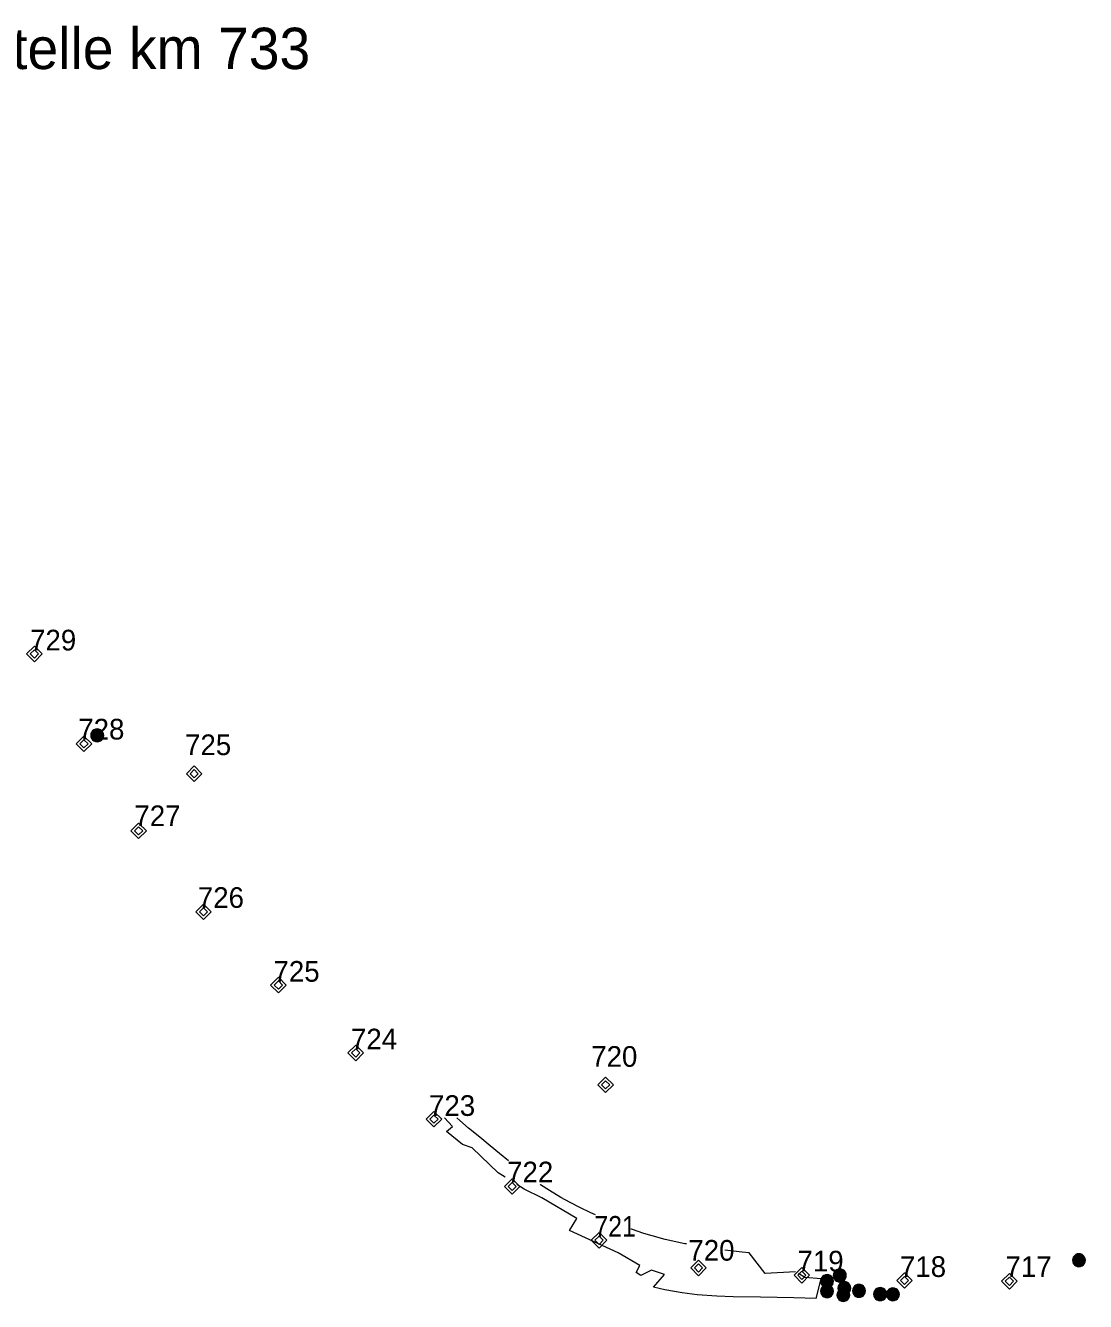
# Model space of a CAD drawing. Extents: x 3461750 to 3585707, y 5917729 to 5985917.
# Drawn here: x 3480178 to 3490431, y 5967330 to 5979672 of the extents above; entities that cross this region are included whole.
import ezdxf

# ---------------------------------------------------------------- set-up
doc = ezdxf.new("R2010")
doc.units = 0
doc.header["$LTSCALE"] = 80
doc.layers.add('11', color=7, linetype='Continuous')
for name, color, linetype, lineweight in [('12', 7, 'Continuous', 13), ('13', 7, 'Continuous', 13), ('14', 7, 'Continuous', 13), ('15', 7, 'Continuous', 13), ('2', 7, 'Continuous', 13), ('3', 7, 'Continuous', 13)]:
    doc.layers.add(name, color=color, linetype=linetype, lineweight=lineweight)

msp = doc.modelspace()

# ---------------------------------------------------------------- hatches: boundary and pattern name
at = {"layer": '3'}
for points in [[(3480934.61, 5972805.43), (3480931.68, 5972822.05), (3480925.43, 5972837.15), (3480915.49, 5972850.11), (3480902.53, 5972860.05), (3480887.44, 5972866.3), (3480871.24, 5972868.43), (3480855.04, 5972866.3), (3480839.95, 5972860.05), (3480826.99, 5972850.11), (3480817.05, 5972837.15), (3480810.8, 5972822.05), (3480808.66, 5972805.86), (3480810.8, 5972789.66), (3480817.05, 5972774.57), (3480826.99, 5972761.61), (3480839.95, 5972751.67), (3480855.04, 5972745.42), (3480871.24, 5972743.28), (3480887.44, 5972745.42), (3480902.53, 5972751.67), (3480915.49, 5972761.61), (3480925.43, 5972774.57), (3480931.68, 5972789.66)], [(3490431.29, 5967728.57), (3490428.36, 5967745.2), (3490422.11, 5967760.29), (3490412.17, 5967773.25), (3490399.21, 5967783.2), (3490384.12, 5967789.45), (3490367.92, 5967791.58), (3490351.72, 5967789.45), (3490336.63, 5967783.2), (3490323.67, 5967773.25), (3490313.73, 5967760.29), (3490307.48, 5967745.2), (3490305.34, 5967729), (3490307.48, 5967712.81), (3490313.73, 5967697.72), (3490323.67, 5967684.76), (3490336.63, 5967674.81), (3490351.72, 5967668.56), (3490367.92, 5967666.43), (3490384.12, 5967668.56), (3490399.21, 5967674.81), (3490412.17, 5967684.76), (3490422.11, 5967697.72), (3490428.36, 5967712.81)], [(3487994.96, 5967526.52), (3487992.03, 5967543.15), (3487985.78, 5967558.24), (3487975.84, 5967571.2), (3487962.88, 5967581.14), (3487947.79, 5967587.4), (3487931.59, 5967589.53), (3487915.4, 5967587.4), (3487900.3, 5967581.14), (3487887.34, 5967571.2), (3487877.4, 5967558.24), (3487871.15, 5967543.15), (3487869.02, 5967526.95), (3487871.15, 5967510.76), (3487877.4, 5967495.67), (3487887.34, 5967482.71), (3487900.3, 5967472.76), (3487915.4, 5967466.51), (3487931.59, 5967464.38), (3487947.79, 5967466.51), (3487962.88, 5967472.76), (3487975.84, 5967482.71), (3487985.78, 5967495.67), (3487992.03, 5967510.76)], [(3488117.72, 5967581.7), (3488114.79, 5967598.32), (3488108.54, 5967613.42), (3488098.59, 5967626.38), (3488085.63, 5967636.32), (3488070.54, 5967642.57), (3488054.35, 5967644.7), (3488038.15, 5967642.57), (3488023.06, 5967636.32), (3488010.1, 5967626.38), (3488000.15, 5967613.42), (3487993.9, 5967598.32), (3487991.77, 5967582.13), (3487993.9, 5967565.93), (3488000.15, 5967550.84), (3488010.1, 5967537.88), (3488023.06, 5967527.94), (3488038.15, 5967521.69), (3488054.35, 5967519.55), (3488070.54, 5967521.69), (3488085.63, 5967527.94), (3488098.59, 5967537.88), (3488108.54, 5967550.84), (3488114.79, 5967565.93)], [(3487994.82, 5967429.26), (3487991.89, 5967445.88), (3487985.64, 5967460.98), (3487975.69, 5967473.94), (3487962.73, 5967483.88), (3487947.64, 5967490.13), (3487931.44, 5967492.26), (3487915.25, 5967490.13), (3487900.16, 5967483.88), (3487887.2, 5967473.94), (3487877.25, 5967460.98), (3487871, 5967445.88), (3487868.87, 5967429.69), (3487871, 5967413.49), (3487877.25, 5967398.4), (3487887.2, 5967385.44), (3487900.16, 5967375.5), (3487915.25, 5967369.25), (3487931.44, 5967367.11), (3487947.64, 5967369.25), (3487962.73, 5967375.5), (3487975.69, 5967385.44), (3487985.64, 5967398.4), (3487991.89, 5967413.49)], [(3488152, 5967392.25), (3488149.07, 5967408.87), (3488142.81, 5967423.96), (3488132.87, 5967436.92), (3488119.91, 5967446.87), (3488104.82, 5967453.12), (3488088.62, 5967455.25), (3488072.43, 5967453.12), (3488057.34, 5967446.87), (3488044.38, 5967436.92), (3488034.43, 5967423.96), (3488028.18, 5967408.87), (3488026.05, 5967392.68), (3488028.18, 5967376.48), (3488034.43, 5967361.39), (3488044.38, 5967348.43), (3488057.34, 5967338.48), (3488072.43, 5967332.23), (3488088.62, 5967330.1), (3488104.82, 5967332.23), (3488119.91, 5967338.48), (3488132.87, 5967348.43), (3488142.81, 5967361.39), (3488149.07, 5967376.48)], [(3488162.05, 5967458.36), (3488159.12, 5967474.98), (3488152.87, 5967490.08), (3488142.93, 5967503.04), (3488129.97, 5967512.98), (3488114.88, 5967519.23), (3488098.68, 5967521.36), (3488082.49, 5967519.23), (3488067.39, 5967512.98), (3488054.43, 5967503.04), (3488044.49, 5967490.08), (3488038.24, 5967474.98), (3488036.11, 5967458.79), (3488038.24, 5967442.59), (3488044.49, 5967427.5), (3488054.43, 5967414.54), (3488067.39, 5967404.6), (3488082.49, 5967398.35), (3488098.68, 5967396.21), (3488114.88, 5967398.35), (3488129.97, 5967404.6), (3488142.93, 5967414.54), (3488152.87, 5967427.5), (3488159.12, 5967442.59)], [(3488303.46, 5967432.68), (3488300.53, 5967449.3), (3488294.28, 5967464.39), (3488284.34, 5967477.35), (3488271.38, 5967487.3), (3488256.28, 5967493.55), (3488240.09, 5967495.68), (3488223.89, 5967493.55), (3488208.8, 5967487.3), (3488195.84, 5967477.35), (3488185.9, 5967464.39), (3488179.65, 5967449.3), (3488177.51, 5967433.1), (3488179.65, 5967416.91), (3488185.9, 5967401.82), (3488195.84, 5967388.86), (3488208.8, 5967378.91), (3488223.89, 5967372.66), (3488240.09, 5967370.53), (3488256.28, 5967372.66), (3488271.38, 5967378.91), (3488284.34, 5967388.86), (3488294.28, 5967401.82), (3488300.53, 5967416.91)], [(3488508.2, 5967400.84), (3488505.27, 5967417.47), (3488499.02, 5967432.56), (3488489.07, 5967445.52), (3488476.11, 5967455.46), (3488461.02, 5967461.71), (3488444.82, 5967463.85), (3488428.63, 5967461.71), (3488413.54, 5967455.46), (3488400.58, 5967445.52), (3488390.63, 5967432.56), (3488384.38, 5967417.47), (3488382.25, 5967401.27), (3488384.38, 5967385.07), (3488390.63, 5967369.98), (3488400.58, 5967357.02), (3488413.54, 5967347.08), (3488428.63, 5967340.83), (3488444.82, 5967338.69), (3488461.02, 5967340.83), (3488476.11, 5967347.08), (3488489.07, 5967357.02), (3488499.02, 5967369.98), (3488505.27, 5967385.07)], [(3488631.83, 5967398.98), (3488628.9, 5967415.61), (3488622.65, 5967430.7), (3488612.7, 5967443.66), (3488599.74, 5967453.61), (3488584.65, 5967459.86), (3488568.46, 5967461.99), (3488552.26, 5967459.86), (3488537.17, 5967453.61), (3488524.21, 5967443.66), (3488514.27, 5967430.7), (3488508.01, 5967415.61), (3488505.88, 5967399.41), (3488508.01, 5967383.22), (3488514.27, 5967368.13), (3488524.21, 5967355.17), (3488537.17, 5967345.22), (3488552.26, 5967338.97), (3488568.46, 5967336.84), (3488584.65, 5967338.97), (3488599.74, 5967345.22), (3488612.7, 5967355.17), (3488622.65, 5967368.13), (3488628.9, 5967383.22)]]:
    msp.add_hatch(color=256, dxfattribs=at).paths.add_polyline_path(points)

# ---------------------------------------------------------------- linework, layer by layer
at = {"layer": '12'}
for points in [[(3481808.63, 5972509.77), (3481733.54, 5972434.68), (3481808.63, 5972359.59), (3481883.72, 5972434.68)], [(3481808.63, 5972474.37), (3481768.93, 5972434.68), (3481808.63, 5972394.99), (3481848.32, 5972434.68)]]:
    msp.add_lwpolyline(points, close=True, dxfattribs=at)
at = {"layer": '13'}
for points in [[(3485789.1, 5969500.4), (3485714, 5969425.31), (3485789.1, 5969350.22), (3485864.19, 5969425.31)], [(3485789.1, 5969465), (3485749.4, 5969425.31), (3485789.1, 5969385.61), (3485828.79, 5969425.31)]]:
    msp.add_lwpolyline(points, close=True, dxfattribs=at)
at = {"layer": '14'}
for points in [[(3486687.92, 5967729.89), (3486612.83, 5967654.8), (3486687.92, 5967579.71), (3486763.01, 5967654.8)], [(3486687.92, 5967694.49), (3486648.23, 5967654.8), (3486687.92, 5967615.1), (3486727.62, 5967654.8)]]:
    msp.add_lwpolyline(points, close=True, dxfattribs=at)
at = {"layer": '15'}
for points in [[(3480263.9, 5973668.36), (3480188.81, 5973593.27), (3480263.9, 5973518.18), (3480338.99, 5973593.27)], [(3480263.9, 5973632.97), (3480224.21, 5973593.27), (3480263.9, 5973553.58), (3480303.59, 5973593.27)], [(3480742.71, 5972799.13), (3480667.62, 5972724.04), (3480742.71, 5972648.95), (3480817.8, 5972724.04)], [(3480742.71, 5972763.73), (3480703.02, 5972724.04), (3480742.71, 5972684.34), (3480782.4, 5972724.04)], [(3481271.86, 5971958.21), (3481196.77, 5971883.12), (3481271.86, 5971808.03), (3481346.95, 5971883.12)], [(3481271.86, 5971922.81), (3481232.17, 5971883.12), (3481271.86, 5971843.43), (3481311.55, 5971883.12)], [(3481899.1, 5971173.83), (3481824.02, 5971098.74), (3481899.1, 5971023.65), (3481974.2, 5971098.74)], [(3481899.1, 5971138.44), (3481859.41, 5971098.74), (3481899.11, 5971059.05), (3481938.8, 5971098.74)], [(3482623.91, 5970466.41), (3482548.82, 5970391.32), (3482623.91, 5970316.23), (3482699, 5970391.32)], [(3482623.91, 5970431.01), (3482584.22, 5970391.32), (3482623.91, 5970351.63), (3482663.6, 5970391.32)], [(3483371.71, 5969809.28), (3483296.62, 5969734.19), (3483371.71, 5969659.1), (3483446.8, 5969734.19)], [(3483371.71, 5969773.88), (3483332.02, 5969734.19), (3483371.71, 5969694.5), (3483411.4, 5969734.19)], [(3484128.45, 5969168.17), (3484053.36, 5969093.08), (3484128.45, 5969017.99), (3484203.54, 5969093.08)], [(3484128.45, 5969132.77), (3484088.76, 5969093.08), (3484128.45, 5969053.39), (3484168.14, 5969093.08)], [(3484885.34, 5968517.97), (3484810.24, 5968442.88), (3484885.34, 5968367.79), (3484960.43, 5968442.88)], [(3484885.34, 5968482.58), (3484845.64, 5968442.88), (3484885.34, 5968403.19), (3484925.03, 5968442.88)], [(3485725.86, 5967996.78), (3485650.77, 5967921.69), (3485725.86, 5967846.6), (3485800.95, 5967921.69)], [(3485725.86, 5967961.38), (3485686.17, 5967921.69), (3485725.86, 5967882), (3485765.56, 5967921.69)], [(3487687.97, 5967658.89), (3487612.88, 5967583.8), (3487687.97, 5967508.71), (3487763.06, 5967583.8)], [(3487687.97, 5967623.49), (3487648.28, 5967583.8), (3487687.97, 5967544.11), (3487727.66, 5967583.8)], [(3488681.14, 5967608.11), (3488606.05, 5967533.02), (3488681.14, 5967457.93), (3488756.23, 5967533.02)], [(3489695.54, 5967600.88), (3489620.45, 5967525.79), (3489695.54, 5967450.7), (3489770.63, 5967525.79)], [(3488681.14, 5967572.71), (3488641.44, 5967533.02), (3488681.14, 5967493.33), (3488720.83, 5967533.02)], [(3489695.54, 5967565.49), (3489655.85, 5967525.79), (3489695.54, 5967486.1), (3489735.23, 5967525.79)]]:
    msp.add_lwpolyline(points, close=True, dxfattribs=at)
at = {"layer": '2'}
for points in [[(3484816.5, 5968533.05), (3484748.44, 5968575.98), (3484499.8, 5968815.14), (3484403.66, 5968847.75), (3484249.51, 5968974.71), (3484308.4, 5969022.27), (3484231.51, 5969105.2)], [(3484849.45, 5968692), (3484762.6, 5968761.13), (3484672.27, 5968834.28), (3484571.34, 5968917.97), (3484462.89, 5969007.23), (3484377.64, 5969080.57), (3484349.37, 5969105.2)], [(3486252.39, 5967467.09), (3486360.5, 5967591.5), (3486234.03, 5967632.52), (3486130.32, 5967582.03), (3486084.47, 5967610.35), (3486121.68, 5967676.86), (3485909.91, 5967802.25), (3485439.16, 5968016.7), (3485510.79, 5968132.81), (3485173.1, 5968331.84), (3485002.98, 5968415.43), (3484929.14, 5968462)], [(3485692.77, 5968166.8), (3485645.17, 5968188.77), (3485539.5, 5968238.67), (3485445.02, 5968288.87), (3485355.91, 5968337.11), (3485248.1, 5968402.25), (3485159.47, 5968459.67), (3485156.12, 5968462)], [(3486570.2, 5967886.35), (3486556.98, 5967888.77), (3486364.89, 5967928.91), (3486239.06, 5967963.67), (3486158.64, 5967988.57), (3486040.43, 5968028.52), (3486033.9, 5968030.88)], [(3487179.15, 5967799.22), (3487109.96, 5967805.57), (3486943.8, 5967825.8)], [(3487625.3, 5967616.61), (3487333.59, 5967599.22), (3487179.15, 5967799.22)], [(3487825.54, 5967357.91), (3487874.07, 5967549.51), (3487717.33, 5967562.99), (3487655.35, 5967600.5)], [(3487825.54, 5967357.91), (3487609.86, 5967363.87), (3487286.28, 5967372.27), (3487023.34, 5967374.71), (3486866.75, 5967380.37), (3486674.51, 5967395.02), (3486528.91, 5967413.48), (3486361.72, 5967443.36), (3486252.39, 5967467.09)]]:
    msp.add_lwpolyline(points, dxfattribs=at)
at = {"layer": '3'}
for points in [[(3480934.61, 5972805.43), (3480931.68, 5972822.05), (3480925.43, 5972837.15), (3480915.49, 5972850.11), (3480902.53, 5972860.05), (3480887.44, 5972866.3), (3480871.24, 5972868.43), (3480855.04, 5972866.3), (3480839.95, 5972860.05), (3480826.99, 5972850.11), (3480817.05, 5972837.15), (3480810.8, 5972822.05), (3480808.66, 5972805.86), (3480810.8, 5972789.66), (3480817.05, 5972774.57), (3480826.99, 5972761.61), (3480839.95, 5972751.67), (3480855.04, 5972745.42), (3480871.24, 5972743.28), (3480887.44, 5972745.42), (3480902.53, 5972751.67), (3480915.49, 5972761.61), (3480925.43, 5972774.57), (3480931.68, 5972789.66)], [(3490431.29, 5967728.57), (3490428.36, 5967745.2), (3490422.11, 5967760.29), (3490412.17, 5967773.25), (3490399.21, 5967783.2), (3490384.12, 5967789.45), (3490367.92, 5967791.58), (3490351.72, 5967789.45), (3490336.63, 5967783.2), (3490323.67, 5967773.25), (3490313.73, 5967760.29), (3490307.48, 5967745.2), (3490305.34, 5967729), (3490307.48, 5967712.81), (3490313.73, 5967697.72), (3490323.67, 5967684.76), (3490336.63, 5967674.81), (3490351.72, 5967668.56), (3490367.92, 5967666.43), (3490384.12, 5967668.56), (3490399.21, 5967674.81), (3490412.17, 5967684.76), (3490422.11, 5967697.72), (3490428.36, 5967712.81)], [(3487994.96, 5967526.52), (3487992.03, 5967543.15), (3487985.78, 5967558.24), (3487975.84, 5967571.2), (3487962.88, 5967581.14), (3487947.79, 5967587.4), (3487931.59, 5967589.53), (3487915.4, 5967587.4), (3487900.3, 5967581.14), (3487887.34, 5967571.2), (3487877.4, 5967558.24), (3487871.15, 5967543.15), (3487869.02, 5967526.95), (3487871.15, 5967510.76), (3487877.4, 5967495.67), (3487887.34, 5967482.71), (3487900.3, 5967472.76), (3487915.4, 5967466.51), (3487931.59, 5967464.38), (3487947.79, 5967466.51), (3487962.88, 5967472.76), (3487975.84, 5967482.71), (3487985.78, 5967495.67), (3487992.03, 5967510.76)], [(3488117.72, 5967581.7), (3488114.79, 5967598.32), (3488108.54, 5967613.42), (3488098.59, 5967626.38), (3488085.63, 5967636.32), (3488070.54, 5967642.57), (3488054.35, 5967644.7), (3488038.15, 5967642.57), (3488023.06, 5967636.32), (3488010.1, 5967626.38), (3488000.15, 5967613.42), (3487993.9, 5967598.32), (3487991.77, 5967582.13), (3487993.9, 5967565.93), (3488000.15, 5967550.84), (3488010.1, 5967537.88), (3488023.06, 5967527.94), (3488038.15, 5967521.69), (3488054.35, 5967519.55), (3488070.54, 5967521.69), (3488085.63, 5967527.94), (3488098.59, 5967537.88), (3488108.54, 5967550.84), (3488114.79, 5967565.93)], [(3487994.82, 5967429.26), (3487991.89, 5967445.88), (3487985.64, 5967460.98), (3487975.69, 5967473.94), (3487962.73, 5967483.88), (3487947.64, 5967490.13), (3487931.44, 5967492.26), (3487915.25, 5967490.13), (3487900.16, 5967483.88), (3487887.2, 5967473.94), (3487877.25, 5967460.98), (3487871, 5967445.88), (3487868.87, 5967429.69), (3487871, 5967413.49), (3487877.25, 5967398.4), (3487887.2, 5967385.44), (3487900.16, 5967375.5), (3487915.25, 5967369.25), (3487931.44, 5967367.11), (3487947.64, 5967369.25), (3487962.73, 5967375.5), (3487975.69, 5967385.44), (3487985.64, 5967398.4), (3487991.89, 5967413.49)], [(3488152, 5967392.25), (3488149.07, 5967408.87), (3488142.81, 5967423.96), (3488132.87, 5967436.92), (3488119.91, 5967446.87), (3488104.82, 5967453.12), (3488088.62, 5967455.25), (3488072.43, 5967453.12), (3488057.34, 5967446.87), (3488044.38, 5967436.92), (3488034.43, 5967423.96), (3488028.18, 5967408.87), (3488026.05, 5967392.68), (3488028.18, 5967376.48), (3488034.43, 5967361.39), (3488044.38, 5967348.43), (3488057.34, 5967338.48), (3488072.43, 5967332.23), (3488088.62, 5967330.1), (3488104.82, 5967332.23), (3488119.91, 5967338.48), (3488132.87, 5967348.43), (3488142.81, 5967361.39), (3488149.07, 5967376.48)], [(3488162.05, 5967458.36), (3488159.12, 5967474.98), (3488152.87, 5967490.08), (3488142.93, 5967503.04), (3488129.97, 5967512.98), (3488114.88, 5967519.23), (3488098.68, 5967521.36), (3488082.49, 5967519.23), (3488067.39, 5967512.98), (3488054.43, 5967503.04), (3488044.49, 5967490.08), (3488038.24, 5967474.98), (3488036.11, 5967458.79), (3488038.24, 5967442.59), (3488044.49, 5967427.5), (3488054.43, 5967414.54), (3488067.39, 5967404.6), (3488082.49, 5967398.35), (3488098.68, 5967396.21), (3488114.88, 5967398.35), (3488129.97, 5967404.6), (3488142.93, 5967414.54), (3488152.87, 5967427.5), (3488159.12, 5967442.59)], [(3488303.46, 5967432.68), (3488300.53, 5967449.3), (3488294.28, 5967464.39), (3488284.34, 5967477.35), (3488271.38, 5967487.3), (3488256.28, 5967493.55), (3488240.09, 5967495.68), (3488223.89, 5967493.55), (3488208.8, 5967487.3), (3488195.84, 5967477.35), (3488185.9, 5967464.39), (3488179.65, 5967449.3), (3488177.51, 5967433.1), (3488179.65, 5967416.91), (3488185.9, 5967401.82), (3488195.84, 5967388.86), (3488208.8, 5967378.91), (3488223.89, 5967372.66), (3488240.09, 5967370.53), (3488256.28, 5967372.66), (3488271.38, 5967378.91), (3488284.34, 5967388.86), (3488294.28, 5967401.82), (3488300.53, 5967416.91)], [(3488508.2, 5967400.84), (3488505.27, 5967417.47), (3488499.02, 5967432.56), (3488489.07, 5967445.52), (3488476.11, 5967455.46), (3488461.02, 5967461.71), (3488444.82, 5967463.85), (3488428.63, 5967461.71), (3488413.54, 5967455.46), (3488400.58, 5967445.52), (3488390.63, 5967432.56), (3488384.38, 5967417.47), (3488382.25, 5967401.27), (3488384.38, 5967385.07), (3488390.63, 5967369.98), (3488400.58, 5967357.02), (3488413.54, 5967347.08), (3488428.63, 5967340.83), (3488444.82, 5967338.69), (3488461.02, 5967340.83), (3488476.11, 5967347.08), (3488489.07, 5967357.02), (3488499.02, 5967369.98), (3488505.27, 5967385.07)], [(3488631.83, 5967398.98), (3488628.9, 5967415.61), (3488622.65, 5967430.7), (3488612.7, 5967443.66), (3488599.74, 5967453.61), (3488584.65, 5967459.86), (3488568.46, 5967461.99), (3488552.26, 5967459.86), (3488537.17, 5967453.61), (3488524.21, 5967443.66), (3488514.27, 5967430.7), (3488508.01, 5967415.61), (3488505.88, 5967399.41), (3488508.01, 5967383.22), (3488514.27, 5967368.13), (3488524.21, 5967355.17), (3488537.17, 5967345.22), (3488552.26, 5967338.97), (3488568.46, 5967336.84), (3488584.65, 5967338.97), (3488599.74, 5967345.22), (3488612.7, 5967355.17), (3488622.65, 5967368.13), (3488628.9, 5967383.22)]]:
    msp.add_lwpolyline(points, close=True, dxfattribs=at)

# ---------------------------------------------------------------- texts
at = {"layer": '11'}
msp.add_text('Klappstelle km 733 ', height=400, dxfattribs=at).set_placement((3478412.8, 5979251))
at = {"layer": '12'}
msp.add_text('725', height=200, dxfattribs=at).set_placement((3481721.3, 5972614.9))
at = {"layer": '13'}
msp.add_text('720', height=200, dxfattribs=at).set_placement((3485650, 5969600))
at = {"layer": '14'}
msp.add_text('720', height=200, dxfattribs=at).set_placement((3486590.2, 5967724.8))
at = {"layer": '15'}
for s, p in [('729', (3480222, 5973627.5)), ('728', (3480688.2, 5972766)), ('727', (3481231.1, 5971928.1)), ('726', (3481844.7, 5971137.4)), ('725', (3482576.5, 5970423.4)), ('724', (3483325.9, 5969768.4)), ('723', (3484081.2, 5969125.2)), ('722', (3484836.5, 5968482)), ('719', (3487645.3, 5967620.5)), ('718', (3488636.7, 5967567.4)), ('717', (3489657.5, 5967567.4))]:
    msp.add_text(s, height=200, dxfattribs=at).set_placement(p)
at = {"layer": '15', "width": 0.9}
msp.add_text('721', height=200, dxfattribs=at).set_placement((3485680.3, 5967956.8))

doc.saveas('drawing.dxf')
